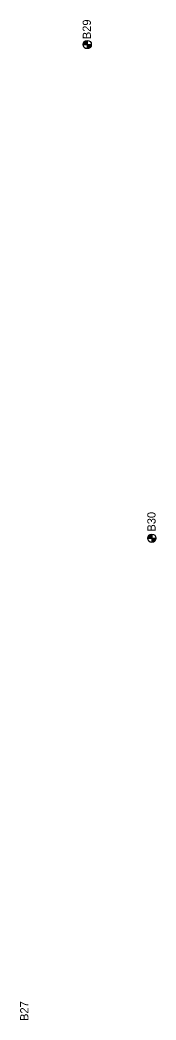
# Model space of a CAD drawing. Extents: x 345549 to 379569, y 127949 to 230467.
# Drawn here: x 361861 to 362026, y 143932 to 145145 of the extents above; entities that cross this region are included whole.
import ezdxf

# ---------------------------------------------------------------- set-up
doc = ezdxf.new("R2010")
doc.units = 0
for name, color, linetype in [('E_SOIL_BORE1 [KAPUR_CADDS_LEVELS]', 7, 'Continuous'), ('E_SOIL_BORE2 [KAPUR_CADDS_LEVELS]', 7, 'Continuous'), ('P_MARK', 7, 'Continuous')]:
    doc.layers.add(name, color=color, linetype=linetype)

msp = doc.modelspace()

# ---------------------------------------------------------------- linework, layer by layer
at = {"layer": 'P_MARK'}
for p, q in [((361937.3, 145115.6), (361947.3, 145115.6)), ((361942.3, 145120.6), (361942.3, 145110.6)), ((362015.7, 144516.7), (362025.7, 144516.7)), ((362020.7, 144521.7), (362020.7, 144511.7))]:
    msp.add_line(p, q, dxfattribs=at)
for centre in [(361942.3, 145115.6), (362020.7, 144516.7)]:
    msp.add_circle(centre, 5, dxfattribs=at)
for centre, radius, start, end in [((361942.3, 145115.6), 4.5, 89.9869, 179.9869), ((361942.3, 145115.6), 4, 89.9869, 179.9869), ((361942.3, 145115.6), 3.5, 89.9869, 179.9869), ((361942.3, 145115.6), 3, 89.9869, 179.9869), ((361942.3, 145115.6), 2.5, 89.9869, 179.9869), ((361942.3, 145115.6), 2, 89.9869, 179.9869), ((361942.3, 145115.6), 1.5, 89.9869, 179.9869), ((361942.3, 145115.6), 1, 89.9869, 179.9869), ((361942.3, 145115.6), 0.5, 89.9869, 179.9869), ((361942.3, 145115.6), 4.5, 269.9869, 359.9869), ((361942.3, 145115.6), 4, 269.9869, 359.9869), ((361942.3, 145115.6), 3.5, 269.9869, 359.9869), ((361942.3, 145115.6), 3, 269.9869, 359.9869), ((361942.3, 145115.6), 2.5, 269.9869, 359.9869), ((361942.3, 145115.6), 2, 269.9869, 359.9869), ((361942.3, 145115.6), 1.5, 269.9869, 359.9869), ((361942.3, 145115.6), 1, 269.9869, 359.9869), ((361942.3, 145115.6), 0.5, 269.9869, 359.9869), ((362020.7, 144516.7), 4.5, 89.9869, 179.9869), ((362020.7, 144516.7), 4, 89.9869, 179.9869), ((362020.7, 144516.7), 3.5, 89.9869, 179.9869), ((362020.7, 144516.7), 3, 89.9869, 179.9869), ((362020.7, 144516.7), 2.5, 89.9869, 179.9869), ((362020.7, 144516.7), 2, 89.9869, 179.9869), ((362020.7, 144516.7), 1.5, 89.9869, 179.9869), ((362020.7, 144516.7), 1, 89.9869, 179.9869), ((362020.7, 144516.7), 0.5, 89.9869, 179.9869), ((362020.7, 144516.7), 4.5, 269.9869, 359.9869), ((362020.7, 144516.7), 4, 269.9869, 359.9869), ((362020.7, 144516.7), 3.5, 269.9869, 359.9869), ((362020.7, 144516.7), 3, 269.9869, 359.9869), ((362020.7, 144516.7), 2.5, 269.9869, 359.9869), ((362020.7, 144516.7), 2, 269.9869, 359.9869), ((362020.7, 144516.7), 1.5, 269.9869, 359.9869), ((362020.7, 144516.7), 1, 269.9869, 359.9869), ((362020.7, 144516.7), 0.5, 269.9869, 359.9869)]:
    msp.add_arc(centre, radius, start, end, dxfattribs=at)

# ---------------------------------------------------------------- texts
at = {"layer": 'E_SOIL_BORE1 [KAPUR_CADDS_LEVELS]'}
for s, p in [('B30', (362025.2, 144524.8)), ('B27', (361871, 143931.2))]:
    msp.add_text(s, height=10, rotation=89.9869, dxfattribs=at).set_placement(p)
at = {"layer": 'E_SOIL_BORE2 [KAPUR_CADDS_LEVELS]'}
msp.add_text('B29', height=10, rotation=89.9869, dxfattribs=at).set_placement((361946.8, 145122.2))

doc.saveas('drawing.dxf')
